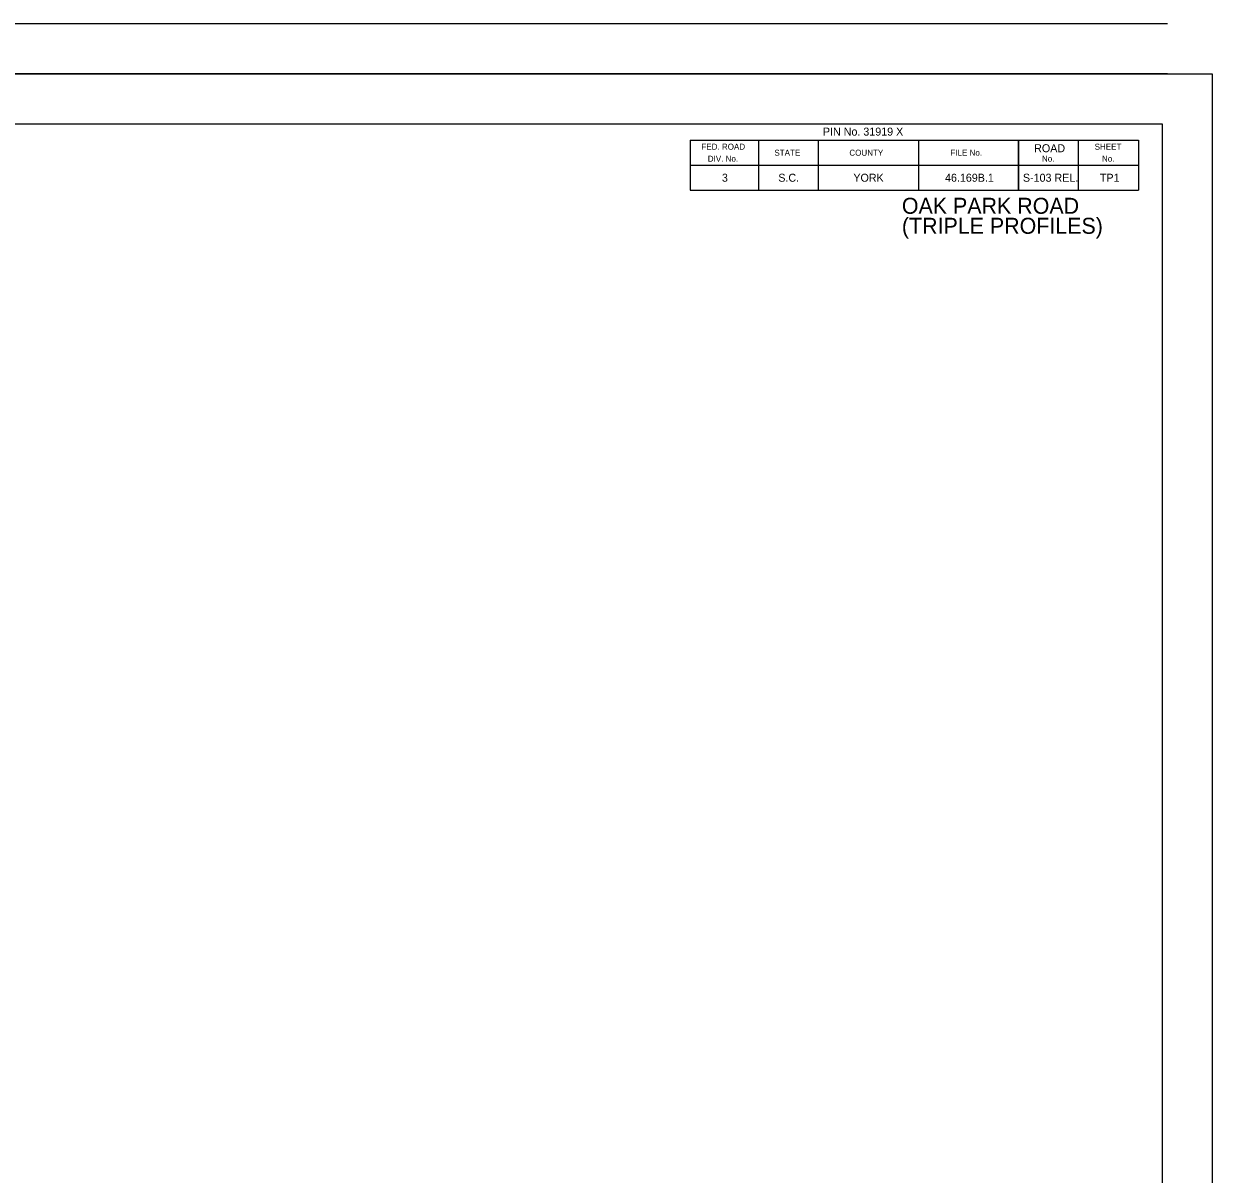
# Model space of a CAD drawing. Extents: x 49817 to 52197, y 49938 to 51088.
# Drawn here: x 51019 to 51613, y 50513 to 51088 of the extents above; entities that cross this region are included whole.
import ezdxf

# ---------------------------------------------------------------- set-up
doc = ezdxf.new("R2010")
doc.units = 0
for name, color, linetype in [('RD_SHT_Bndy', 7, 'Continuous'), ('RD_SHT_Iplotshp', 7, 'Continuous'), ('RD_SHT_TX', 7, 'Continuous')]:
    doc.layers.add(name, color=color, linetype=linetype)

msp = doc.modelspace()

# ---------------------------------------------------------------- linework, layer by layer
at = {"layer": 'RD_SHT_Bndy'}
for p, q in [((51590.65, 51087.5), (49830.65, 51087.5)), ((51590.65, 51062.5), (49830.65, 51062.5)), ((51352.15, 51029.3), (51352.15, 51004.3)), ((51352.15, 51029.3), (51516.15, 51029.3)), ((51386.15, 51029.3), (51386.15, 51004.3)), ((51416.15, 51004.3), (51416.15, 51029.3)), ((51466.15, 51029.3), (51466.15, 51004.3)), ((51516.15, 51004.3), (51516.15, 51029.3)), ((51516.15, 51029.3), (51516.15, 51004.3)), ((51516.15, 51029.3), (51576.15, 51029.3)), ((51546.15, 51004.3), (51546.15, 51029.3)), ((51576.15, 51029.3), (51576.15, 51004.3)), ((51352.15, 51016.8), (51516.15, 51016.8)), ((51516.15, 51016.8), (51576.15, 51016.8)), ((51352.15, 51004.3), (51516.15, 51004.3)), ((51516.15, 51004.3), (51576.15, 51004.3))]:
    msp.add_line(p, q, dxfattribs=at)
msp.add_lwpolyline([(49913.05, 51037.5), (51588, 51037.5), (51588, 49987.5), (49913.05, 49987.5)], close=True, dxfattribs=at)
at = {"layer": 'RD_SHT_Iplotshp'}
msp.add_lwpolyline([(49817.1, 51062.5), (51613, 51062.5), (51613, 49962.5), (49817.1, 49962.5)], close=True, dxfattribs=at)

# ---------------------------------------------------------------- texts
at = {"layer": 'RD_SHT_TX'}
for s, height, p in [('PIN No. 31919 X   ', 4, (51418.42, 51031.6)), ('FED. ROAD', 3, (51357.7, 51024.55)), ('STATE', 3, (51394.17, 51021.55)), ('COUNTY', 3, (51431.64, 51021.55)), ('FILE No.', 3, (51482.15, 51021.55)), ('      ROAD      ', 4, (51515.09, 51023.29)), ('SHEET', 3, (51554.23, 51024.55)), ('DIV. No.', 3, (51360.89, 51018.55)), ('No.', 3, (51527.91, 51018.55)), ('No.', 3, (51557.91, 51018.55)), ('3', 4, (51367.95, 51008.55)), ('S.C.', 4, (51396.13, 51008.55)), ('      YORK     ', 4, (51424.74, 51008.55)), ('   46.169B.1    ', 4, (51474.99, 51008.55)), ('   S-103 REL.   ', 4, (51513.93, 51008.55)), ('      TP1       ', 4, (51547.93, 51008.55)), ('OAK PARK ROAD', 8, (51457.89, 50992.53)), ('(TRIPLE PROFILES)', 8, (51457.89, 50982.53))]:
    msp.add_text(s, height=height, dxfattribs=at).set_placement(p)

doc.saveas('drawing.dxf')
